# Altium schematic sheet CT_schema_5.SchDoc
size 298 x 247 mm
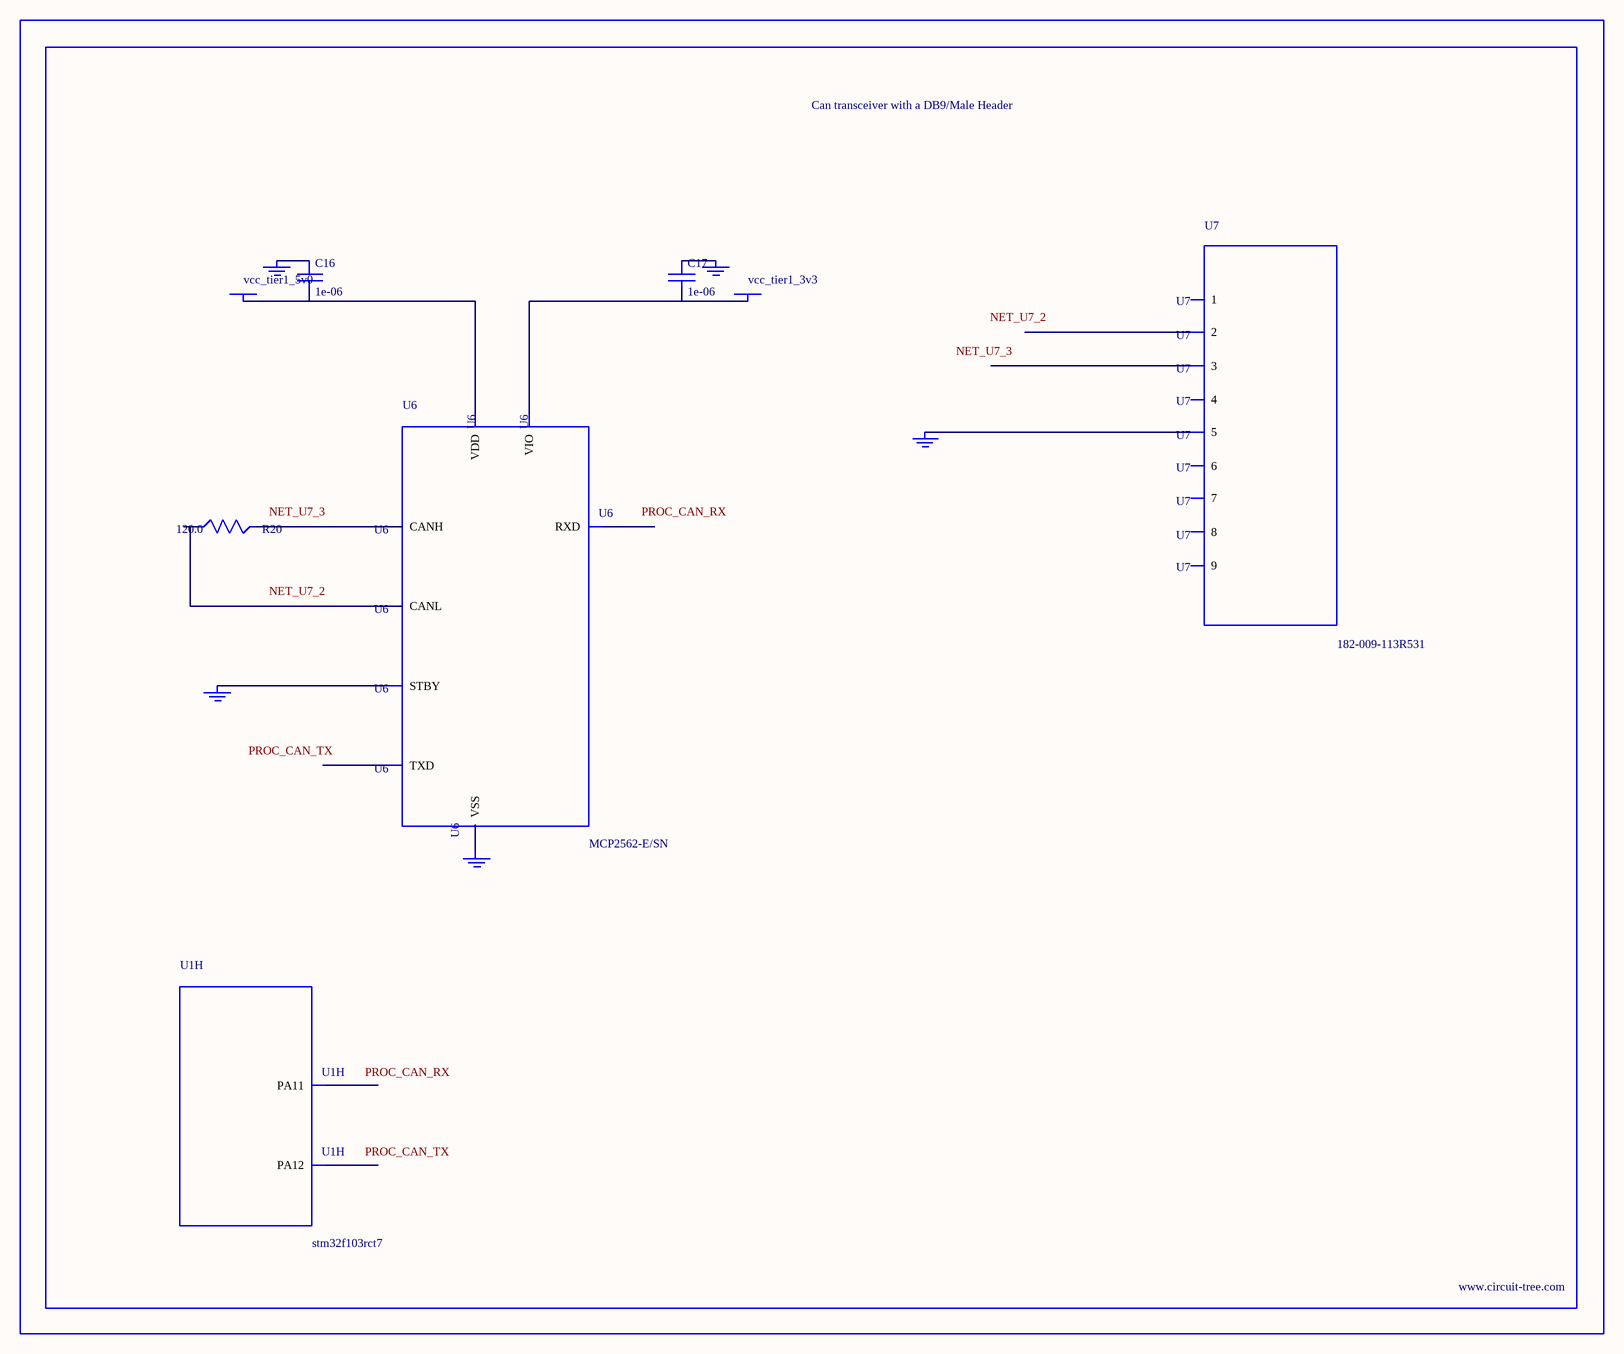
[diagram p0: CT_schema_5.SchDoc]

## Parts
BORDER4  (no value)
C16  1e-06  [C0603]
C17  1e-06  [C0603]
GND_INSTANCE_4_0  (no value)
GND_INSTANCE_4_1  (no value)
GND_INSTANCE_4_2  (no value)
GND_INSTANCE_4_3  (no value)
GND_INSTANCE_4_4  (no value)
POWER_INSTANCE_4_0  vcc_tier1_5v0
POWER_INSTANCE_4_1  vcc_tier1_3v3
R20  120.0  [R0603]
U1  stm32f103rct7  [LQFP64]  (part H of 9)
U6  MCP2562-E/SN  [SOIC-8]
U7  182-009-113R531  [182-009-MALE]

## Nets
NetC16_1: C16.1 GND_INSTANCE_4_0.0(GND)
NetC16_2: C16.2 POWER_INSTANCE_4_0.0(PWR) U6.3(VDD)
NetC17_1: C17.1 GND_INSTANCE_4_1.0(GND)
NetC17_2: C17.2 POWER_INSTANCE_4_1.0(PWR) U6.5(VIO)
NetGND_INSTANCE_4_2_0: GND_INSTANCE_4_2.0(GND) U6.8(STBY)
NetGND_INSTANCE_4_3_0: GND_INSTANCE_4_3.0(GND) U6.2(VSS)
NetGND_INSTANCE_4_4_0: GND_INSTANCE_4_4.0(GND) U7.5
NetR20_1: R20.1 U6.6(CANL)
NetR20_2: R20.2 U6.7(CANH)

Not connected (* = marked no-connect by the designer): U1 44(PA11) 45(PA12); U6 1(TXD) 4(RXD); U7 1 2 3 4 6 7 8 9

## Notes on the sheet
- Labels drawn without touching a wire or pin: NET_U7_2, NET_U7_3, PROC_CAN_RX, PROC_CAN_TX

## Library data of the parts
BORDER4 = BORDER_PAGE4
C16 C17 = C0603C105K3RACTU
GND_INSTANCE_4_0-GND_INSTANCE_4_4 = GND
POWER_INSTANCE_4_0 POWER_INSTANCE_4_1 = PWR
R20 = RC0603JR-07120RL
